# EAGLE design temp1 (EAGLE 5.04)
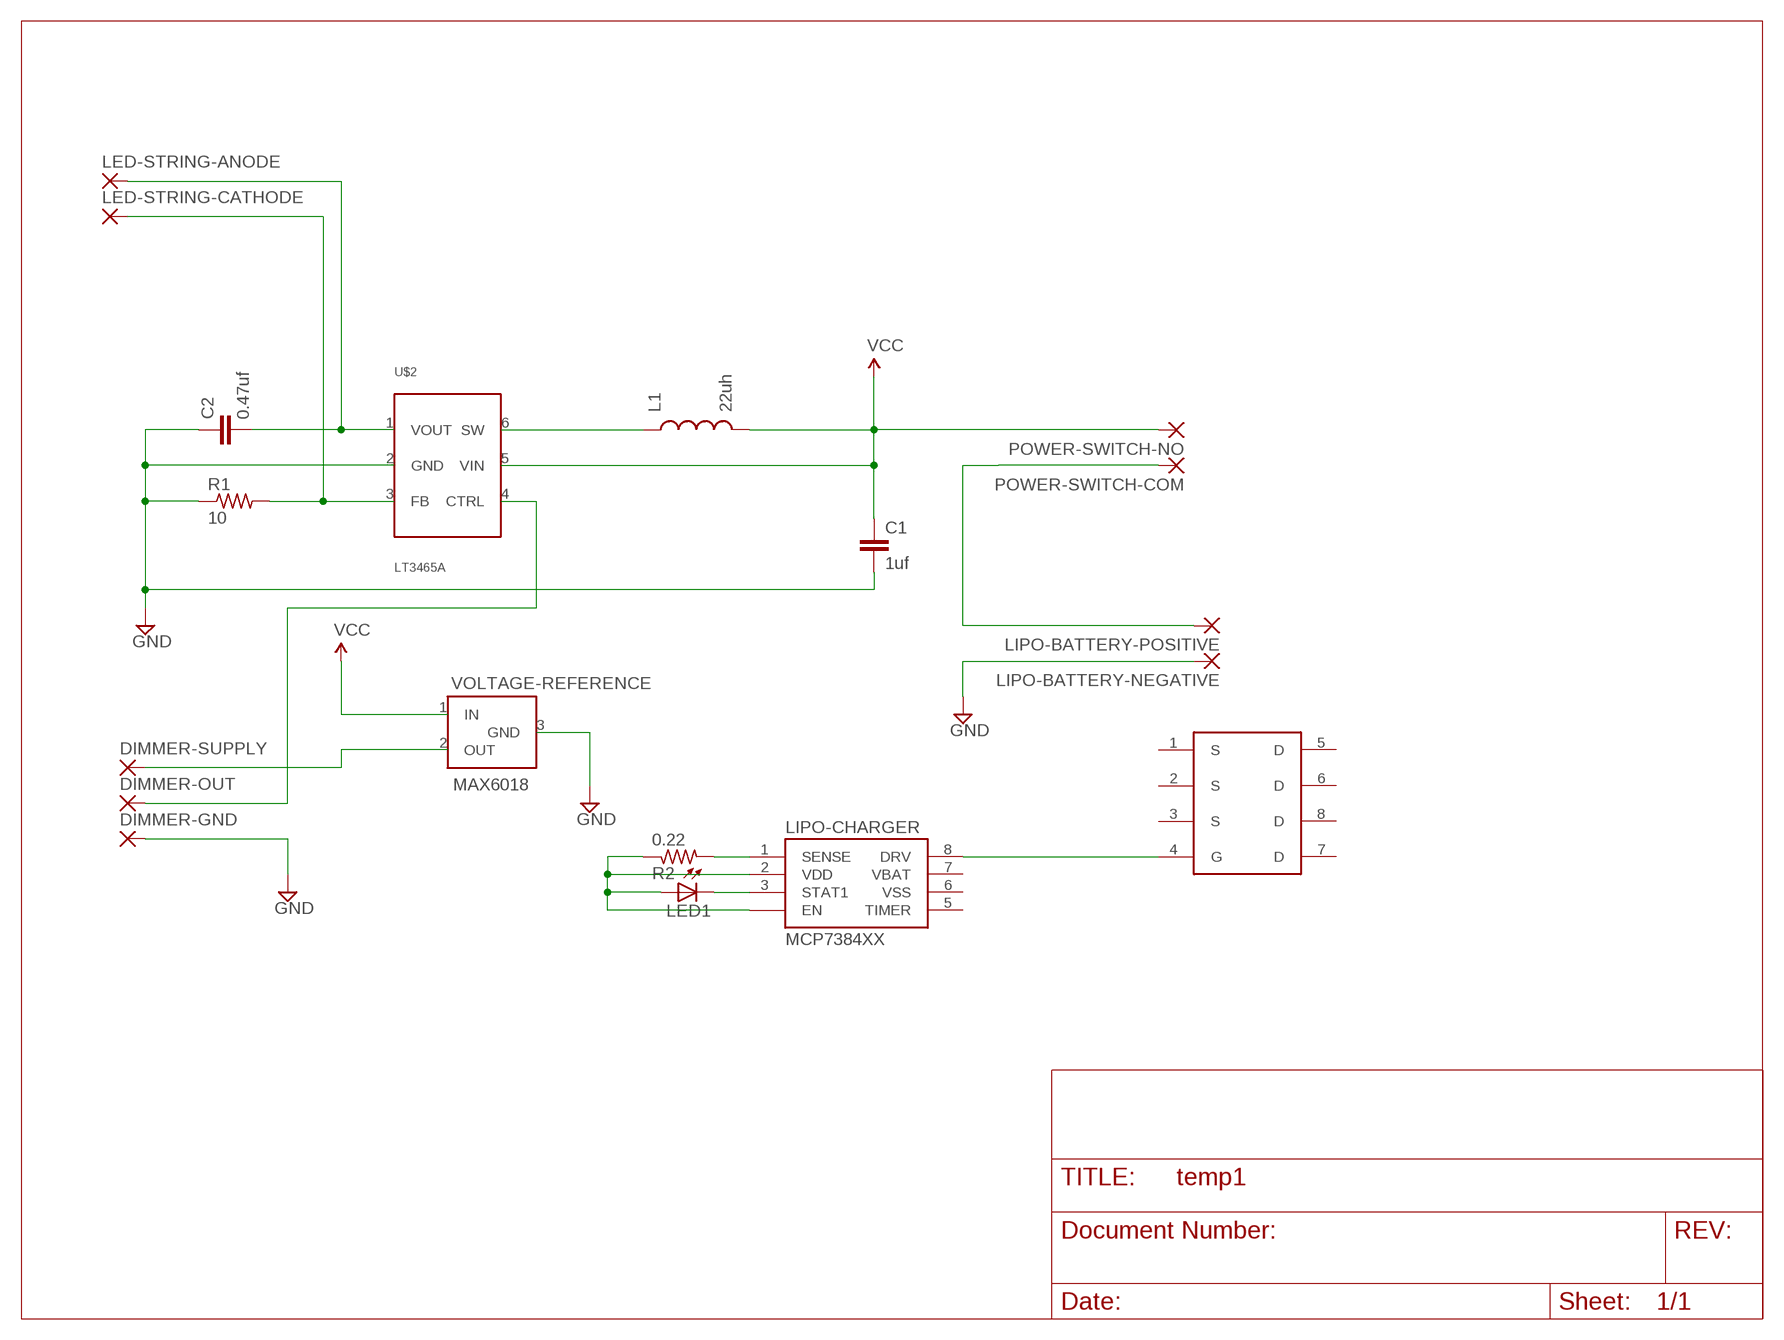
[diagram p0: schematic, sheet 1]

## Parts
C1  1uf  C-EUC1005  [C1005]
C2  0.47uf  C-EUC1005  [C1005]
DIMMER-GND  WIREPADSMD5-2,5  [5-2,5]
DIMMER-OUT  WIREPADSMD5-2,5  [5-2,5]
DIMMER-SUPPLY  WIREPADSMD5-2,5  [5-2,5]
L1  22uh  INDUCTOR1210  [1210]
LED1  LEDSFH480  [SFH480]
LED-STRING-ANODE  WIREPADSMD5-2,5  [5-2,5]
LED-STRING-CATHODE  WIREPADSMD5-2,5  [5-2,5]
LIPO-BATTERY-NEGATIVE  WIREPADSMD5-2,5  [5-2,5]
LIPO-BATTERY-POSITIVE  WIREPADSMD5-2,5  [5-2,5]
LIPO-CHARGER  MCP7384XX  [MSOP8]
POWER-SWITCH-COM  WIREPADSMD5-2,5  [5-2,5]
POWER-SWITCH-NO  WIREPADSMD5-2,5  [5-2,5]
R1  10  R-US_M2012  [M2012]
R2  0.22  R-US_M2012  [M2012]
U$1  NDS8434  [SO08]
U$2  LT3465A  [SOT23-6]
VOLTAGE-REFERENCE  MAX6018  [SOT23-3]

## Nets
GND: C1.2 C2.1 DIMMER-GND.1(P) LIPO-BATTERY-NEGATIVE.1(P) R1.1 U$2.2(GND) VOLTAGE-REFERENCE.3(GND)
N$1: L1.1 U$2.6(SW)
N$2: C2.2 LED-STRING-ANODE.1(P) U$2.1(VOUT)
N$3: DIMMER-SUPPLY.1(P) VOLTAGE-REFERENCE.2(OUT)
N$4: LED-STRING-CATHODE.1(P) R1.2 U$2.3(FB)
N$5: DIMMER-OUT.1(P) U$2.4(CTRL)
N$6: LIPO-BATTERY-POSITIVE.1(P) POWER-SWITCH-COM.1(P)
N$7: LIPO-CHARGER.1(SENSE) R2.2
N$8: LIPO-CHARGER.8(DRV) U$1.4(G)
N$9: LED1.A LIPO-CHARGER.2(VDD) LIPO-CHARGER.4(EN) R2.1
N$10: LED1.K(C) LIPO-CHARGER.3(STAT1)
VCC: C1.1 L1.2 POWER-SWITCH-NO.1(P) U$2.5(VIN) VOLTAGE-REFERENCE.1(IN)
Unconnected: LIPO-CHARGER.5(TIMER) LIPO-CHARGER.6(VSS) LIPO-CHARGER.7(VBAT) U$1.1(S) U$1.2(S) U$1.3(S) U$1.5(D) U$1.6(D) U$1.7(D) U$1.8(D)

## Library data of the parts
C1 C2 = rcl:C-EU: CAPACITOR, European symbol
DIMMER-GND DIMMER-OUT DIMMER-SUPPLY LED-STRING-ANODE LED-STRING-CATHODE LIPO-BATTERY-NEGATIVE LIPO-BATTERY-POSITIVE POWER-SWITCH-COM POWER-SWITCH-NO = wirepad:WIREPAD: Wire PAD connect wire on PCB
L1 = SparkFun:INDUCTOR: Inductors
LED1 = led:LED: LED
LIPO-CHARGER = SparkFun:MCP7384XX
R1 R2 = resistor:R-US_: RESISTOR, American symbol
U$1 = SparkFun:NDS8434
U$2 = trl:LT3465A
VOLTAGE-REFERENCE = trl:MAX6018

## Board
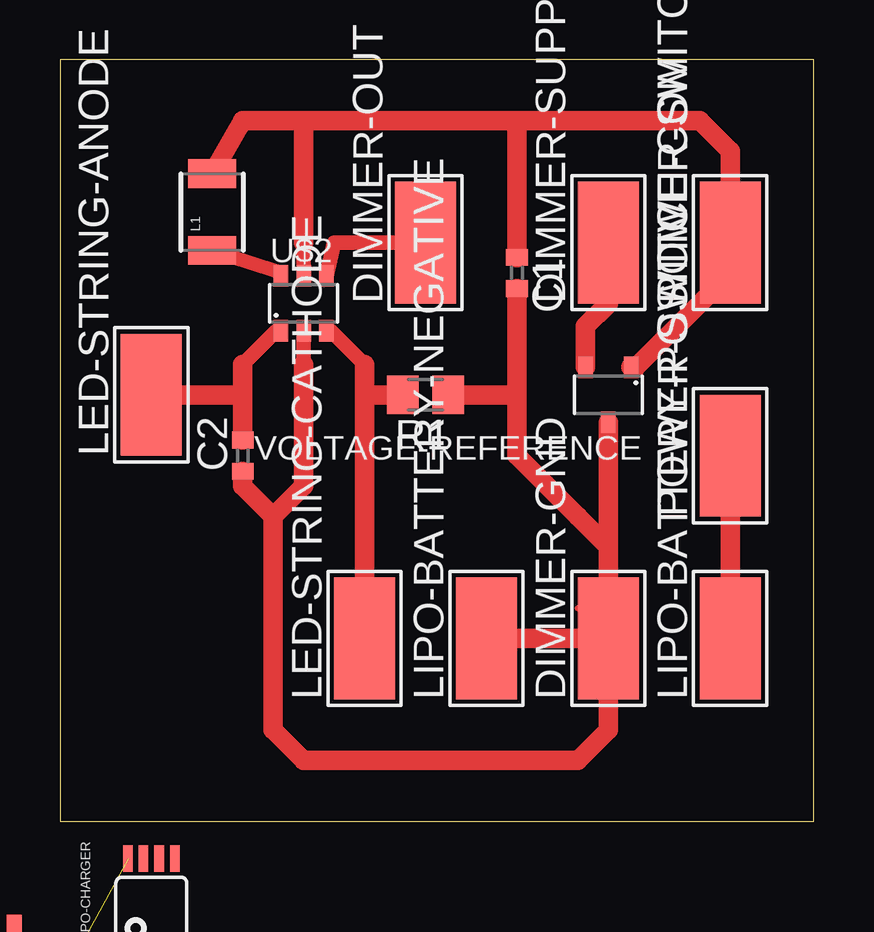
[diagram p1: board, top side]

Size 31.42 x 31.74 mm. Coordinates in mm from the lower left corner, seen from the top.
Outline: 0,0 31.42,0 31.42,31.74 0,31.74 0,0
Copper layers (1*16): Top 0.035mm / dielectric 1.5mm / Bottom 0.035mm
Design rules "default": minimum track width 10mil, minimum drill 24mil, track to track 8mil, track to pad 8mil, pad to pad 8mil, via to via 8mil, smd to smd 8mil, copper to edge 40mil, drill to drill 8mil, minimum pad ring 10mil, minimum via ring 8mil, stop-mask expansion 4mil, vias tented up to drill 0mil, thermal gap 10mil

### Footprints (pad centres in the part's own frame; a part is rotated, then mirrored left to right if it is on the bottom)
C1005 = smd 0.7 x 0.9: 1 -0.65,0; 2 0.65,0
5-2,5 = smd 2.54 x 5.08: 1 0,0
1210 = smd 1.2 x 2: 1 -1.6,0; 2 1.6,0
SFH480 = drill 0.813 long: A 1.27,0; K -1.27,0
MSOP8 = smd 0.4 x 1.1: 1 -0.975,-2.25; 2 -0.325,-2.25; 3 0.325,-2.25; 4 0.975,-2.25; 5 0.975,2.25; 6 0.325,2.25; 7 -0.325,2.25; 8 -0.975,2.25
M2012 = smd 1.3 x 1.6: 1 -0.95,0; 2 0.95,0
SO08 = smd 0.61 x 2.21: 1 -1.905,-2.616; 2 -0.635,-2.616; 3 0.635,-2.616; 4 1.905,-2.616; 5 1.905,2.616; 6 0.635,2.616; 7 -0.635,2.616; 8 -1.905,2.616
SOT23-6 = smd 0.6 x 0.9: 1 -0.95,-1.15; 2 0,-1.15; 3 0.95,-1.15; 4 0.95,1.15; 5 0,1.15; 6 -0.95,1.15
SOT23-3 = smd 0.6 x 0.9: 1 -0.95,-1.15; 2 0.95,-1.15; 3 0,1.15

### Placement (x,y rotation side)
C1  19.05,22.86 270 top
C2  7.62,15.24 90 top
DIMMER-GND  22.86,7.62 0 top
DIMMER-OUT  15.24,24.13 0 top
DIMMER-SUPPLY  22.86,24.13 0 top
L1  6.35,25.4 90 top
LED1  not placed on the board
LED-STRING-ANODE  3.81,17.78 0 top
LED-STRING-CATHODE  12.7,7.62 0 top
LIPO-BATTERY-NEGATIVE  17.78,7.62 0 top
LIPO-BATTERY-POSITIVE  27.94,7.62 0 top
LIPO-CHARGER  3.81,-3.81 0 top
POWER-SWITCH-COM  27.94,15.24 0 top
POWER-SWITCH-NO  27.94,24.13 0 top
R1  15.24,17.78 180 top
R2  not placed on the board
U$1  not placed on the board
U$2  10.16,21.59 0 top
VOLTAGE-REFERENCE  22.86,17.78 180 top

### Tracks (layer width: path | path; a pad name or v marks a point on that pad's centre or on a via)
GND
  Top 0.254: U$2.2 10.16,20.32 | DIMMER-GND.1 21.59,8.89
  Top 0.61: 10.16,19.05 U$2.2
  Top 0.813: DIMMER-GND.1 LIPO-BATTERY-NEGATIVE.1 | 22.86,11.43 22.86,10.16 DIMMER-GND.1 | 22.86,11.43 21.59,12.7 19.05,15.24 19.05,16.51 19.05,17.78 | 19.05,17.78 19.05,20.32 19.05,21.59 C1.2 | 10.16,19.05 10.16,13.97 8.89,12.7 | 8.89,12.7 8.89,11.43 8.89,3.81 10.16,2.54 21.59,2.54 22.86,3.81 DIMMER-GND.1 | 8.89,12.7 7.62,13.97 C2.1 | 22.86,11.43 VOLTAGE-REFERENCE.3 | 19.05,17.78 R1.1
N$1
  Top 0.406: U$2.6 9.21,22.87
  Top 0.61: 9.21,22.87 L1.1
N$2
  Top 0.61: U$2.1 9.01,20.44 7.62,19.05
  Top 0.813: 7.62,17.78 7.62,16.51 C2.2 | 7.62,17.78 7.62,19.05 | LED-STRING-ANODE.1 7.62,17.78
N$3
  Top 0.813: VOLTAGE-REFERENCE.2 21.91,20.64 22.86,21.59 DIMMER-SUPPLY.1
N$4
  Top 0.61: U$2.3 11.31,20.44 12.7,19.05
  Top 0.813: LED-STRING-CATHODE.1 12.7,17.78 | 12.7,17.78 12.7,19.05 | 12.7,17.78 R1.2
N$5
  Top 0.61: U$2.4 11.43,24.13 DIMMER-OUT.1
N$6
  Top 0.813: POWER-SWITCH-COM.1 LIPO-BATTERY-POSITIVE.1
N$7  (1 unrouted)
N$8  (1 unrouted)
N$9  (3 unrouted)
N$10  (1 unrouted)
VCC
  Top 0.254: U$2.5 10.16,22.86
  Top 0.61: 10.16,22.86 10.16,24.13
  Top 0.813: C1.1 19.05,29.21 17.78,29.21 | 10.16,29.21 7.62,29.21 L1.2 | 10.16,29.21 17.78,29.21 | 17.78,29.21 26.67,29.21 27.94,27.94 POWER-SWITCH-NO.1 27.94,22.86 26.67,21.59 24.01,18.93 VOLTAGE-REFERENCE.1 | 10.16,24.13 10.16,29.21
